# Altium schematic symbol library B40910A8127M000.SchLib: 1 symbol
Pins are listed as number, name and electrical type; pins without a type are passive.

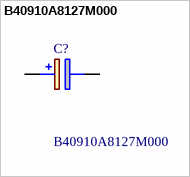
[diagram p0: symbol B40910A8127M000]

## B40910A8127M000
designator C?
63V, 120uF (M) d10x12,5 mm SMD HP; Manufacturer_Name: TDK; Geometry.Height: 12.8mm
footprint B40910A8127M000
pins: 1 +, 2 -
